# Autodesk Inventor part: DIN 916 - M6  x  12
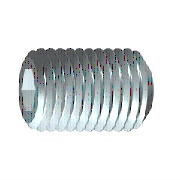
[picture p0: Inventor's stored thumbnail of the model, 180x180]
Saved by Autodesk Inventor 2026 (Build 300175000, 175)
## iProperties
IsCustomPart: 1
Created: 2021-02
Part Number: DIN 916 - M6  x  12
Material: Silver
Description: Hexagon Socket Set Screw
Document SubType Name: Modeling
Standard: DIN 916
Designer: Lars Bertram Pedersen
Standards Organization: DIN
Language: en-US
Size Designation: M6  x  12
Categories: <MemberInstance><Categories><Category DisplayName="Fasteners" InternalName="e4da775c-781d-43d5-af7c-5136215cf5a6" Mnemonic="FSTN"><Category DisplayName="Bolts"
Density: 10.49 g/cm^3
Appearance: Silver
Mass: 2.9986 g
Surface Area: 2.98175 cm^2
Volume: 0.285854 cm^3
Author: Lars Bertram Pedersen
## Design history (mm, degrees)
revolve "Body" stored, may be unused: angle "d6" = 90 deg
sketch "Sketch2"
  geometry: L1 (1.732, 0)-(0.866, -1.5); L2 (0.866, -1.5)-(-0.866, -1.5); L3 (-0.866, -1.5)-(-1.732, 0); L4 (-1.732, 0)-(-0.866, 1.5); L5 (-0.866, 1.5)-(0.866, 1.5); L6 (0.866, 1.5)-(1.732, 0); C1 r 3 at (0, 0) reference; A1 r 1.732 centre (0, 0) between (1.732, 0) and (0.866, -1.5) reference; 1 further point
  constraints: 12 end point, 2 point on circle, 1 coincident, 1 horizontal, 11 other
extrude "Slot" join sketch "Sketch2" distance "d8" = 3.5 (= INTI); taper "d9" = 0 deg
workaxis "Work Axis1"
workplane "Work Plane1"
body "Solid1"
chamfer "Chamfer1" distance "d10" = 1.5 (= -0.5 x SPD + 0.5 x NND); stored, may be unused: angle "d11" = 45 deg (= FAWI), second distance "d33" = 1.5 (= -0.5 x SPD + 0.5 x NND)
feature "Thread" dims "d14" = 12 (= NLG), "d15" = 0
chamfer "Chamfer2" distance "d12" = 0.61345 (= -0.5 x GD1 + 0.5 x NND); stored, may be unused: angle "d13" = 45 deg (= FAWI), second distance "d34" = 0.61345 (= -0.5 x GD1 + 0.5 x NND)
sketch "Sketch1"
  geometry: L1 (0.866, 0)-(7.5, 0); L2 (12, 1.732)-(12, 3); L3 (12, 3)-(0, 3); L4 (12, 1.732)-(8.5, 1.732); L5 (8.5, 1.732)-(7.5, 0); L6 (0, 1.5)-(0.866, 0); L7 (0, -0.6)-(0, 3.6) reference; L8 (0, 1.5)-(0, 3); 1 further point
  constraints: 14 end point, 2 parallel, 2 perpendicular, 1 horizontal, 1 midpoint, 1 point on line
  dimensions: "d0" = 3.5 distance of L2.start L4.end (= INTI); "d1" = 60 deg angle of L5 L1; "d2" = 6 diameter of L3 L1 (= NND); "d3" = 3.4641 diameter of L4 L1 (= 1.1547 x SW); "d4" = 12 distance from line of L2 L6.start (= NLG); "d5" = 60 deg angle of L1 L6 (= 0.5 x ANG); "d7" = 3 diameter of L6.start L1 (= SPD)
other parameters: "NND" = 6 [user parameter; used in 5 equation terms], "NLG" = 12 [user parameter; used in 2 equation terms], "INTI" = 3.5 [user parameter; used in 2 equation terms], "FAWI" = 45 deg [user parameter; used in 2 equation terms], "SW" = 3 [user parameter; used in 2 equation terms], "GD1" = 4.7731 (= THREADDIA - 1.2269 x PTC) [user parameter; used in 2 equation terms], "ANG" = 120 deg [user parameter; used in 1 equation term], "FAWI1" = 45 deg [user parameter], "SPD" = 3 [user parameter; used in 3 equation terms], "d16" = 0, "d35" = 0, "d37" = 0, "GUL" = 0.61345 (= 0.61345 x PTC) [user parameter], "TOA" = 30 deg [user parameter], "THREADDIA" = 6 [user parameter; used in 1 equation term], "PTC" = 1 [user parameter; used in 4 equation terms], "GAL" = 0.61345 (= 0.61345 x PTC) [user parameter], "E0" = 3.465 (= 1.155 x SW) [user parameter]
